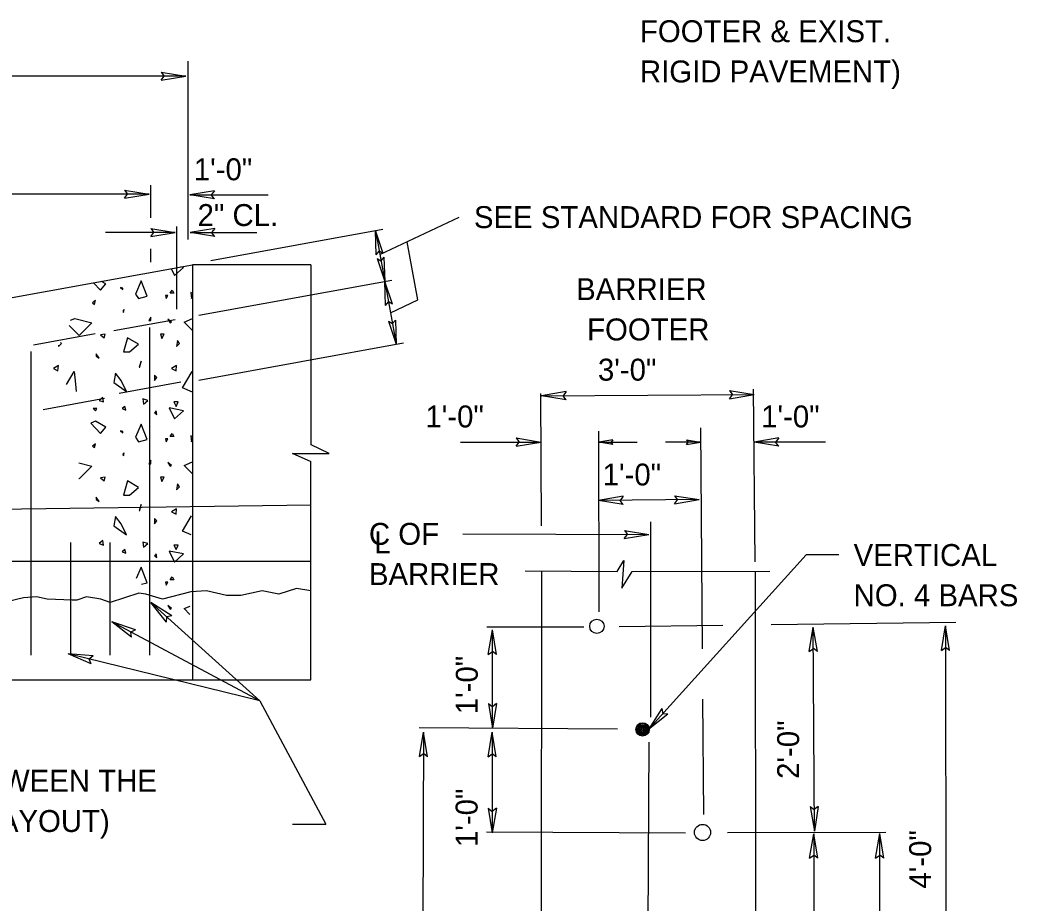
# Model space of a CAD drawing. Extents: x -0.8 to 6.5, y 10.6 to 20.8.
# Drawn here: x 3.625 to 6.35, y 14.693 to 17.108 of the extents above; entities that cross this region are included whole.
import ezdxf

# ---------------------------------------------------------------- set-up
doc = ezdxf.new("R2010")
doc.units = 0
for name, color, linetype in [('DETL-DIMS', 7, 'Continuous'), ('DETL-LINE', 7, 'Continuous'), ('DETL-NOTE', 7, 'Continuous'), ('DETL-PATT', 7, 'Continuous')]:
    doc.layers.add(name, color=color, linetype=linetype)

msp = doc.modelspace()

# ---------------------------------------------------------------- linework, layer by layer
at = {"layer": 'DETL-DIMS'}
for p, q in [((4.0849, 16.5072), (4.0849, 16.9945)), ((4.0784, 16.9541), (1.9522, 16.9541)), ((4.011, 16.9653), (4.0784, 16.9541)), ((4.011, 16.9653), (4.0195, 16.9541)), ((4.011, 16.9428), (4.0784, 16.9541)), ((4.011, 16.9428), (4.0195, 16.9541)), ((3.983, 16.5669), (3.983, 16.6555)), ((3.9782, 16.6314), (2.0037, 16.6314)), ((3.9109, 16.6425), (3.9782, 16.6314)), ((3.9109, 16.6425), (3.9194, 16.6314)), ((3.9109, 16.6202), (3.9782, 16.6314)), ((3.9109, 16.6202), (3.9194, 16.6314)), ((4.1567, 16.6405), (4.0895, 16.6294)), ((4.0895, 16.6294), (4.3042, 16.6294)), ((4.1567, 16.6182), (4.0895, 16.6294)), ((4.1567, 16.6405), (4.1483, 16.6294)), ((4.1567, 16.6182), (4.1483, 16.6294)), ((4.6091, 16.4659), (4.8261, 16.5685)), ((4.054, 16.3166), (4.054, 16.5429)), ((4.05, 16.5264), (3.8596, 16.5264)), ((3.9827, 16.5377), (4.05, 16.5264)), ((3.9827, 16.5377), (3.9912, 16.5264)), ((3.9827, 16.5152), (4.05, 16.5264)), ((3.9827, 16.5152), (3.9912, 16.5264)), ((4.1577, 16.5377), (4.0905, 16.5264)), ((4.0905, 16.5264), (4.2727, 16.5264)), ((4.1577, 16.5152), (4.0905, 16.5264)), ((4.1472, 16.4497), (4.6168, 16.5352)), ((4.1577, 16.5377), (4.1492, 16.5264)), ((4.1577, 16.5152), (4.1492, 16.5264)), ((4.5993, 16.4656), (4.5971, 16.5315)), ((4.6181, 16.4689), (4.5971, 16.5315)), ((4.5971, 16.5315), (4.6224, 16.3929)), ((4.7129, 16.3424), (4.6839, 16.5014)), ((3.983, 16.4457), (3.983, 16.4821)), ((4.5993, 16.4656), (4.6073, 16.4754)), ((4.6181, 16.4689), (4.6073, 16.4754)), ((4.6199, 16.4589), (4.6121, 16.4491)), ((4.6199, 16.4589), (4.6224, 16.3929)), ((4.6013, 16.4554), (4.6224, 16.3929)), ((4.6013, 16.4554), (4.6121, 16.4491)), ((4.1147, 16.3004), (4.6421, 16.3964)), ((4.6224, 16.3929), (4.6536, 16.2211)), ((4.6246, 16.3269), (4.6224, 16.3929)), ((4.6433, 16.3302), (4.6224, 16.3929)), ((4.6246, 16.3269), (4.6324, 16.3367)), ((4.6433, 16.3302), (4.6324, 16.3367)), ((4.6381, 16.3069), (4.7129, 16.3424)), ((4.6324, 16.2836), (4.6536, 16.2211)), ((4.6324, 16.2836), (4.6433, 16.2773)), ((4.6513, 16.2871), (4.6433, 16.2773)), ((4.6513, 16.2871), (4.6536, 16.2211)), ((4.1147, 16.1229), (4.6733, 16.2246)), ((5.0482, 16.0866), (5.0497, 15.7248)), ((5.1179, 16.0913), (5.0507, 16.0798)), ((5.0507, 16.0798), (5.6319, 16.0833)), ((5.118, 16.069), (5.0507, 16.0798)), ((5.1179, 16.0913), (5.1095, 16.0801)), ((5.118, 16.069), (5.1095, 16.0801)), ((5.5646, 16.0941), (5.6319, 16.0833)), ((5.5646, 16.0941), (5.5731, 16.083)), ((5.5648, 16.0716), (5.6319, 16.0833)), ((5.5648, 16.0716), (5.5731, 16.083)), ((5.6349, 15.6262), (5.6304, 16.0985)), ((5.2087, 15.4894), (5.207, 15.9835)), ((5.4851, 15.9921), (5.4901, 15.3882)), ((4.8297, 15.9535), (5.0487, 15.9535)), ((4.9815, 15.9646), (5.0487, 15.9535)), ((4.9815, 15.9646), (4.99, 15.9535)), ((4.9815, 15.9423), (5.0487, 15.9535)), ((4.9815, 15.9423), (4.99, 15.9535)), ((5.2455, 15.9598), (5.2072, 15.9535)), ((5.2072, 15.9535), (5.3118, 15.9535)), ((5.2455, 15.9471), (5.2072, 15.9535)), ((5.2455, 15.9598), (5.2407, 15.9535)), ((5.2455, 15.9471), (5.2407, 15.9535)), ((5.4855, 15.9535), (5.3898, 15.9535)), ((5.447, 15.9598), (5.4855, 15.9535)), ((5.447, 15.9598), (5.4518, 15.9535)), ((5.447, 15.9471), (5.4855, 15.9535)), ((5.447, 15.9471), (5.4518, 15.9535)), ((5.6991, 15.9646), (5.6319, 15.9535)), ((5.8272, 15.9535), (5.6319, 15.9535)), ((5.6991, 15.9423), (5.6319, 15.9535)), ((5.6991, 15.9646), (5.6906, 15.9535)), ((5.6991, 15.9423), (5.6906, 15.9535)), ((5.2737, 15.8053), (5.2067, 15.7933)), ((5.2737, 15.8053), (5.2655, 15.794)), ((5.4143, 15.8067), (5.4816, 15.7962)), ((5.4143, 15.8067), (5.4228, 15.7955)), ((5.4816, 15.7962), (5.2067, 15.7933)), ((5.274, 15.7828), (5.2067, 15.7933)), ((5.274, 15.7828), (5.2655, 15.794)), ((5.4145, 15.7842), (5.4816, 15.7962)), ((5.4145, 15.7842), (5.4228, 15.7955)), ((5.3485, 15.735), (5.3488, 15.2013)), ((4.8357, 15.7023), (5.3443, 15.7005)), ((5.277, 15.6895), (5.2855, 15.7007)), ((5.277, 15.6895), (5.3443, 15.7005)), ((5.2772, 15.712), (5.3443, 15.7005)), ((5.2772, 15.712), (5.2855, 15.7007)), ((5.7736, 15.6447), (5.3427, 15.1673)), ((5.8637, 15.6447), (5.7736, 15.6447)), ((4.0255, 15.4612), (3.9834, 15.5147)), ((4.0405, 15.4779), (3.9834, 15.5147)), ((3.9834, 15.5147), (4.2812, 15.2463)), ((4.0405, 15.4779), (4.0269, 15.4752)), ((4.2812, 15.2463), (3.8767, 15.4617)), ((3.9307, 15.4202), (3.8767, 15.4617)), ((3.9412, 15.4401), (3.8767, 15.4617)), ((4.0255, 15.4612), (4.0269, 15.4752)), ((5.2632, 15.4489), (5.5465, 15.4524)), ((6.1829, 15.4601), (5.6783, 15.4539)), ((6.1435, 15.3834), (6.1547, 15.4506)), ((6.1547, 15.4506), (6.1565, 14.2871)), ((6.166, 15.3834), (6.1547, 15.4506)), ((3.9412, 15.4401), (3.9285, 15.4341)), ((3.9307, 15.4202), (3.9285, 15.4341)), ((4.9016, 15.4484), (5.1662, 15.4479)), ((4.9054, 15.3729), (4.9166, 15.4401)), ((4.9167, 15.1711), (4.9166, 15.4401)), ((4.9279, 15.3729), (4.9166, 15.4401)), ((5.7826, 15.3804), (5.7934, 15.4477)), ((5.7964, 14.8898), (5.7934, 15.4477)), ((5.8051, 15.3806), (5.7934, 15.4477)), ((4.2812, 15.2463), (3.7576, 15.3742)), ((3.8202, 15.3474), (3.7576, 15.3742)), ((3.8256, 15.3691), (3.7576, 15.3742)), ((3.8256, 15.3691), (3.8147, 15.3602)), ((4.9054, 15.3729), (4.9166, 15.3812)), ((4.9279, 15.3729), (4.9166, 15.3812)), ((5.7826, 15.3804), (5.7937, 15.3889)), ((5.8051, 15.3806), (5.7937, 15.3889)), ((6.1435, 15.3834), (6.1547, 15.3919)), ((6.166, 15.3834), (6.1547, 15.3919)), ((3.8202, 15.3474), (3.8147, 15.3602)), ((4.2812, 15.2463), (4.4613, 14.9088)), ((4.9056, 15.2383), (4.9167, 15.1711)), ((4.9056, 15.2383), (4.9167, 15.2298)), ((4.9279, 15.2383), (4.9167, 15.1711)), ((4.9279, 15.2383), (4.9167, 15.2298)), ((5.494, 14.9355), (5.4913, 15.2509)), ((5.3793, 15.2246), (5.3427, 15.1673)), ((5.396, 15.2096), (5.3427, 15.1673)), ((5.3793, 15.2246), (5.382, 15.2108)), ((5.396, 15.2096), (5.382, 15.2108)), ((5.258, 15.1683), (4.7161, 15.1718)), ((4.7169, 15.0933), (4.7284, 15.1604)), ((4.7284, 15.1604), (4.7241, 13.9861)), ((4.7394, 15.0931), (4.7284, 15.1604)), ((4.9049, 15.0931), (4.9161, 15.1603)), ((4.9161, 15.1603), (4.9162, 14.8848)), ((4.9272, 15.0931), (4.9161, 15.1603)), ((5.344, 15.1333), (5.338, 14.0301)), ((4.7169, 15.0933), (4.7283, 15.1016)), ((4.7394, 15.0931), (4.7283, 15.1016)), ((4.9049, 15.0931), (4.9161, 15.1014)), ((4.9272, 15.0931), (4.9161, 15.1014)), ((4.9049, 14.952), (4.9162, 14.8848)), ((4.9049, 14.952), (4.9162, 14.9435)), ((4.9274, 14.952), (4.9162, 14.8848)), ((4.9274, 14.952), (4.9162, 14.9435)), ((5.7848, 14.957), (5.7964, 14.8898)), ((5.7848, 14.957), (5.7961, 14.9485)), ((5.8072, 14.957), (5.7961, 14.9485)), ((5.8072, 14.957), (5.7964, 14.8898)), ((4.3701, 14.9088), (4.4613, 14.9088)), ((5.4441, 14.8841), (4.9006, 14.8871)), ((5.559, 14.886), (5.9914, 14.8865)), ((5.7834, 14.8153), (5.7946, 14.8825)), ((5.7946, 14.8825), (5.7949, 14.2867)), ((5.8057, 14.8153), (5.7946, 14.8825)), ((5.9637, 14.8157), (5.9749, 14.883)), ((5.9756, 13.7003), (5.9749, 14.883)), ((5.9861, 14.8157), (5.9749, 14.883)), ((5.7834, 14.8153), (5.7946, 14.8237)), ((5.8057, 14.8153), (5.7946, 14.8237)), ((5.9637, 14.8157), (5.9749, 14.8242)), ((5.9861, 14.8157), (5.9749, 14.8242))]:
    msp.add_line(p, q, dxfattribs=at)
at = {"layer": 'DETL-LINE'}
for p, q in [((2.3148, 16.1141), (4.0967, 16.4381)), ((4.4208, 16.4381), (4.0967, 16.4381)), ((4.0967, 16.4381), (4.0967, 15.3037)), ((4.4208, 16.4381), (4.4208, 15.946)), ((3.8816, 16.2581), (4.0497, 16.2888)), ((3.6628, 16.2196), (3.8309, 16.2503)), ((3.9794, 16.2666), (3.9794, 15.3711)), ((3.6554, 16.2009), (3.6554, 15.3711)), ((3.8969, 16.0876), (4.0649, 16.1181)), ((3.6887, 16.0426), (3.8567, 16.0733)), ((4.4706, 15.9226), (4.4216, 15.946)), ((4.3701, 15.9218), (4.4706, 15.9226)), ((4.4216, 15.8993), (4.3701, 15.9218)), ((4.4203, 15.3037), (4.4203, 15.8993)), ((2.314, 15.7522), (4.4203, 15.7817)), ((3.7634, 15.6785), (3.7634, 15.3711)), ((3.8714, 15.6785), (3.8714, 15.3711)), ((2.3148, 15.6282), (4.4203, 15.6282)), ((5.2578, 15.5999), (5.2757, 15.6297)), ((5.2757, 15.6297), (5.27, 15.5544)), ((5.0064, 15.601), (5.2578, 15.5999)), ((5.0487, 13.0051), (5.052, 15.599)), ((5.27, 15.5544), (5.2988, 15.5995)), ((5.2988, 15.5995), (5.6751, 15.6005)), ((5.6349, 15.5982), (5.6368, 13.0051)), ((2.3148, 15.3037), (4.4203, 15.3037))]:
    msp.add_line(p, q, dxfattribs=at)
msp.add_lwpolyline([(4.4203, 15.547), (4.3815, 15.5535), (4.3328, 15.5372), (4.2873, 15.547), (4.229, 15.534), (4.19, 15.534), (4.1348, 15.547), (4.0927, 15.5437), (4.0149, 15.5242), (3.9694, 15.5372), (3.9499, 15.5405), (3.8721, 15.5145), (3.8461, 15.5242), (3.8072, 15.5307), (3.7812, 15.521), (3.7682, 15.521), (3.7001, 15.5242), (3.6709, 15.5307), (3.6353, 15.5275), (3.5931, 15.5177)], dxfattribs=at)
for centre, radius in [((5.202, 15.4497), 0.0196), ((5.3268, 15.1678), 0.0183), ((5.3269, 15.1678), 0.0155), ((5.3269, 15.1669), 0.0122), ((5.3269, 15.1669), 0.00967), ((5.3273, 15.1665), 0.00671), ((5.3273, 15.1665), 0.00588), ((5.3273, 15.1665), 0.00255), ((5.4908, 14.8861), 0.0221)]:
    msp.add_circle(centre, radius, dxfattribs=at)
at = {"layer": 'DETL-PATT'}
for points in [[(4.039, 16.4276), (4.0479, 16.4087), (4.072, 16.4307), (4.0649, 16.4322)], [(3.8267, 16.3891), (3.8459, 16.3684), (3.8602, 16.3861), (3.8486, 16.3929)], [(4.0967, 16.3607), (4.092, 16.3621), (4.0945, 16.3459), (4.0967, 16.3542)], [(3.7634, 16.2868), (3.7752, 16.2916), (3.8219, 16.2796), (3.7872, 16.2451), (3.7602, 16.2721)], [(4.0967, 16.2586), (4.0739, 16.2816), (4.0967, 16.2909)], [(3.7312, 16.2183), (3.7306, 16.2148), (3.7387, 16.2229), (3.7366, 16.2261)], [(3.7524, 16.1106), (3.7734, 16.1461), (3.7772, 16.1116), (3.7787, 16.0921)], [(4.0967, 16.09), (4.07, 16.1015), (4.0964, 16.1461), (4.0967, 16.1433)], [(4.0967, 15.9691), (4.092, 15.9705), (4.0945, 15.9541), (4.0967, 15.9625)], [(3.7867, 15.897), (3.8219, 15.888), (3.7872, 15.8533), (3.7867, 15.854)], [(4.0967, 15.867), (4.0739, 15.8898), (4.0967, 15.8993)], [(4.0937, 15.6997), (4.07, 15.7098), (4.0945, 15.7513)], [(3.9575, 15.5647), (3.973, 15.5687), (3.9567, 15.611), (3.9434, 15.5804)], [(4.0897, 15.4824), (4.0739, 15.4982), (4.0902, 15.5049)]]:
    msp.add_lwpolyline(points, dxfattribs=at)
for points in [[(3.949, 16.3459), (3.973, 16.3521), (3.9567, 16.3942), (3.9409, 16.3582)], [(3.9064, 16.3741), (3.9005, 16.3761), (3.9064, 16.3702)], [(4.0235, 16.3539), (4.0254, 16.3459), (4.0297, 16.3539)], [(4.0417, 16.3684), (4.046, 16.3602), (4.0359, 16.3602)], [(3.8237, 16.3339), (3.8296, 16.3299), (3.8319, 16.3401)], [(3.9107, 16.3156), (3.9064, 16.3118), (3.9087, 16.3074)], [(3.9832, 16.2954), (3.9774, 16.2854), (3.9832, 16.2854)], [(4.0359, 16.2796), (4.0399, 16.2816), (4.0297, 16.2898)], [(3.8459, 16.2469), (3.8559, 16.2388), (3.8579, 16.2489)], [(4.0095, 16.2489), (4.0134, 16.2369), (4.0197, 16.2489)], [(3.9245, 16.2004), (3.949, 16.2211), (3.9189, 16.2388), (3.9087, 16.2004)], [(4.056, 16.2311), (4.0537, 16.2148), (4.0619, 16.2229)], [(3.8339, 16.1946), (3.8339, 16.1884), (3.8421, 16.1826)], [(3.7167, 16.1543), (3.7287, 16.1481), (3.7306, 16.1624)], [(3.951, 16.1581), (3.9529, 16.1581), (3.9567, 16.1744)], [(4.0399, 16.1543), (4.0519, 16.1481), (4.0537, 16.1624)], [(3.8862, 16.1418), (3.8824, 16.1159), (3.9164, 16.0915), (3.9025, 16.1216)], [(3.9932, 16.1361), (3.9932, 16.1216), (3.9995, 16.1298)], [(3.8521, 16.0756), (3.8421, 16.0675), (3.8541, 16.0631)], [(3.9044, 16.0453), (3.9145, 16.041), (3.9125, 16.0511)], [(3.961, 16.0713), (3.963, 16.0573), (3.975, 16.0675)], [(4.046, 16.0631), (4.0519, 16.0511), (4.058, 16.0631)], [(3.8257, 16.0453), (3.8319, 16.0391), (3.8357, 16.0453)], [(3.9932, 16.0328), (3.9995, 16.029), (3.9975, 16.0391)], [(4.0335, 16.0473), (4.0479, 16.017), (4.072, 16.0391)], [(3.8194, 16.005), (3.8459, 15.9766), (3.8602, 15.9945), (3.8319, 16.0108)], [(3.949, 15.9541), (3.973, 15.9605), (3.9567, 16.0026), (3.9409, 15.9666)], [(3.9064, 15.9825), (3.9005, 15.9845), (3.9064, 15.9786)], [(4.0417, 15.9766), (4.046, 15.9685), (4.0359, 15.9685)], [(3.8237, 15.9421), (3.8296, 15.9383), (3.8319, 15.9483)], [(4.0235, 15.9623), (4.0254, 15.9541), (4.0297, 15.9623)], [(3.9107, 15.924), (3.9064, 15.9201), (3.9087, 15.9158)], [(3.9832, 15.9038), (3.9774, 15.8937), (3.9832, 15.8937)], [(4.0359, 15.888), (4.0399, 15.8898), (4.0297, 15.898)], [(3.8459, 15.8553), (3.8559, 15.8472), (3.8579, 15.8572)], [(3.9245, 15.8087), (3.949, 15.8293), (3.9189, 15.8472), (3.9087, 15.8087)], [(4.0095, 15.8572), (4.0134, 15.8452), (4.0197, 15.8572)], [(4.056, 15.8395), (4.0537, 15.8232), (4.0619, 15.8313)], [(3.8339, 15.803), (3.8339, 15.7967), (3.8421, 15.791)], [(3.951, 15.7665), (3.9529, 15.7665), (3.9567, 15.7828)], [(3.8862, 15.7502), (3.8824, 15.7242), (3.9164, 15.6997), (3.9025, 15.73)], [(4.0399, 15.7627), (4.0519, 15.7563), (4.0537, 15.7708)], [(3.9932, 15.7443), (3.9932, 15.73), (3.9995, 15.7382)], [(3.8521, 15.6839), (3.8421, 15.6757), (3.8541, 15.6714)], [(3.961, 15.6795), (3.963, 15.6657), (3.975, 15.6757)], [(4.046, 15.6714), (4.0519, 15.6594), (4.058, 15.6714)], [(3.9044, 15.6537), (3.9145, 15.6494), (3.9125, 15.6594)], [(3.9932, 15.6412), (3.9995, 15.6374), (3.9975, 15.6474)], [(4.0335, 15.6555), (4.0479, 15.6254), (4.072, 15.6474)], [(4.0235, 15.5707), (4.0254, 15.5625), (4.0297, 15.5707)], [(4.0417, 15.585), (4.046, 15.5769), (4.0359, 15.5769)], [(4.0359, 15.4962), (4.0399, 15.4982), (4.0297, 15.5064)]]:
    msp.add_lwpolyline(points, close=True, dxfattribs=at)

# ---------------------------------------------------------------- texts
at = {"layer": 'DETL-NOTE'}
for s, rotation, p in [('FOOTER & EXIST.', 360, (5.3197, 17.0468)), ('RIGID PAVEMENT)', 360, (5.3197, 16.9368)), ('C OF', 360, (4.5791, 15.6724)), ('BARRIER', 360, (4.5791, 15.5624)), ('1\'-0"', 90, (4.8766, 15.2092)), ('2\'-0"', 90, (5.7548, 15.0324)), ('1\'-0"', 90, (4.8761, 14.8461)), ('4\'-0"', 90, (6.1155, 14.7325))]:
    msp.add_text(s, height=0.06, rotation=rotation, dxfattribs=at).set_placement(p)
for s, p in [('1\'-0"', (4.1005, 16.6693)), ('2" CL.', (4.1109, 16.5441)), ('SEE STANDARD FOR SPACING', (4.866, 16.5385)), ('BARRIER', (5.1454, 16.3415)), ('FOOTER', (5.1753, 16.2314)), ('3\'-0"', (5.2049, 16.1214)), ('1\'-0"', (4.7334, 15.9935)), ('1\'-0"', (5.6509, 15.9935)), ('1\'-0"', (5.2178, 15.8347)), ('L', (4.5934, 15.6491)), ('VERTICAL', (5.9036, 15.6146)), ('NO. 4 BARS', (5.9036, 15.5046)), ('4\'-0" C/C. ONE ROW OF THE BARS SHALL BE STAGGERED WITH THE OTHER. CENTER LINE DISTANCE BETWEEN THE', (-0.5645, 14.9974)), ('BARS SHALL BE 2\'-0". THE VERTICAL NO.4 BARS SHALL BE STAGGERED WITH THE NO.8 BARS (SEE BAR LAYOUT)', (-0.5645, 14.8873))]:
    msp.add_text(s, height=0.06, dxfattribs=at).set_placement(p)

doc.saveas('drawing.dxf')
